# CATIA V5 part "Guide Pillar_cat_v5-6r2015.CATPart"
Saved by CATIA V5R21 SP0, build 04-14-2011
Part number: Guide Pillar
Bounding box of the stored display mesh (mm): x 82.5 to 107.5, y 17.51 to 42.49, z 0 to 200
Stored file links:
  E:\cadcim\Projects\CATIA V5-6R2015_Menuscript\WebResources\CATIA V5-6r2015_partfiles\Tutorials\c12_catia_v5_6r2015_tut\c12tut2\Guide Pillar_cat_v5-6r2015.CATPart
  E:\cadcim\Projects\CATIA V5-6R2015_Menuscript\WebResources\CATIA V5-6r2015_partfiles\Tutorials\c12_catia_v5_6r2015_tut\c12tut2\Assembly_cat_v5-6r2015.CATProduct
  D:\CATIA V5R21 E-RESOURCES\CATIA-V5R21\catia-v5r21-Tut\c12-catia-v5r21-tut\c12-catia-v5r21-tut02\Bottom Plate.CATPart
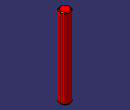
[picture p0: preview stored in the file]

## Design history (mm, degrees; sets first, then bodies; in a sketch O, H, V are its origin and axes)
Set1
  DatumSurface1: linked copy from another document
  DatumCurve1: linked copy from another document
Body1 (main body)
  Sketch1 on face of DatumSurface1, origin (0, 0, 0), H (1, 0, 0), V (0, 1, 0)
    projected circle E1 centre (95, 30) radius 12.5 from edge of DatumCurve1
  Pad1: profile Sketch1, direction (0, 0, 1), length 200
  Chamfer1: length 2, angle 45, on edge [face of Pad1 | face of Pad1] (x2)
